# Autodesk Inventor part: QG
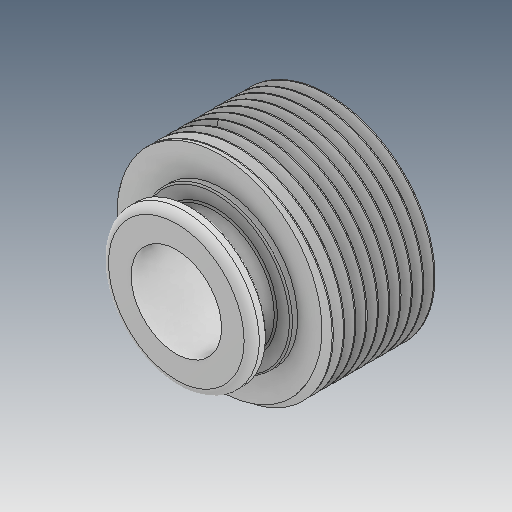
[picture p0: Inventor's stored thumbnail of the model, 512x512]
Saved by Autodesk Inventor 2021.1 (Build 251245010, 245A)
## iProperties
Created: 2021-05
Part Number: QG
Material: Ogólny
Document SubType Name: Modeling
Designer: user
Density: 1 g/cm^3
Appearance: Domyślna
Author: user
Revision Number: ÈÎºÎ
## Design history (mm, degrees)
feature "ÊäÈë1"
node "Bryła1"
